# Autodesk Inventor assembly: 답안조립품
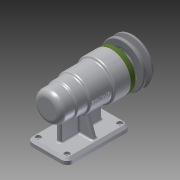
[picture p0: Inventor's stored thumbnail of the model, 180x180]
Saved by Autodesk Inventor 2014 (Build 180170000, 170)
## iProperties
Created: 2016-06
Part Number: 답안조립품
Document SubType Name: Assembly
Designer: USER
Author: USER
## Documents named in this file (12)
- C:\Users\USER\Desktop\460607V1022\답안조립품.iam
- C:\Users\USER\Desktop\460607V1022\본체.ipt
- C:\Users\USER\Desktop\460607V1022\V벨트풀리.ipt
- C:\Users\USER\Desktop\460607V1022\멈춤나사 M3x8.ipt
- C:\Users\USER\Desktop\460607V1022\베어링 6004.ipt
- C:\Users\USER\Desktop\460607V1022\베어링 51202.ipt
- C:\Users\USER\Desktop\460607V1022\볼트 M4 x 12.ipt
- C:\Users\USER\Desktop\460607V1022\어댑터슬리브.ipt
- C:\Users\USER\Desktop\460607V1022\오일 실.ipt
- C:\Users\USER\Desktop\460607V1022\축.ipt
- C:\Users\USER\Desktop\460607V1022\커버.ipt
- C:\Users\USER\Desktop\460607V1022\키 5 x 5 x 16.ipt
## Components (6 placed, 2 different names)
1. V벨트풀리:1
2. ISO 4762 M4 x 12:1
3. ISO 4762 M4 x 12:2
4. ISO 4762 M4 x 12:3
5. ISO 4762 M4 x 12:4
6. ISO 4762 M4 x 12:5
